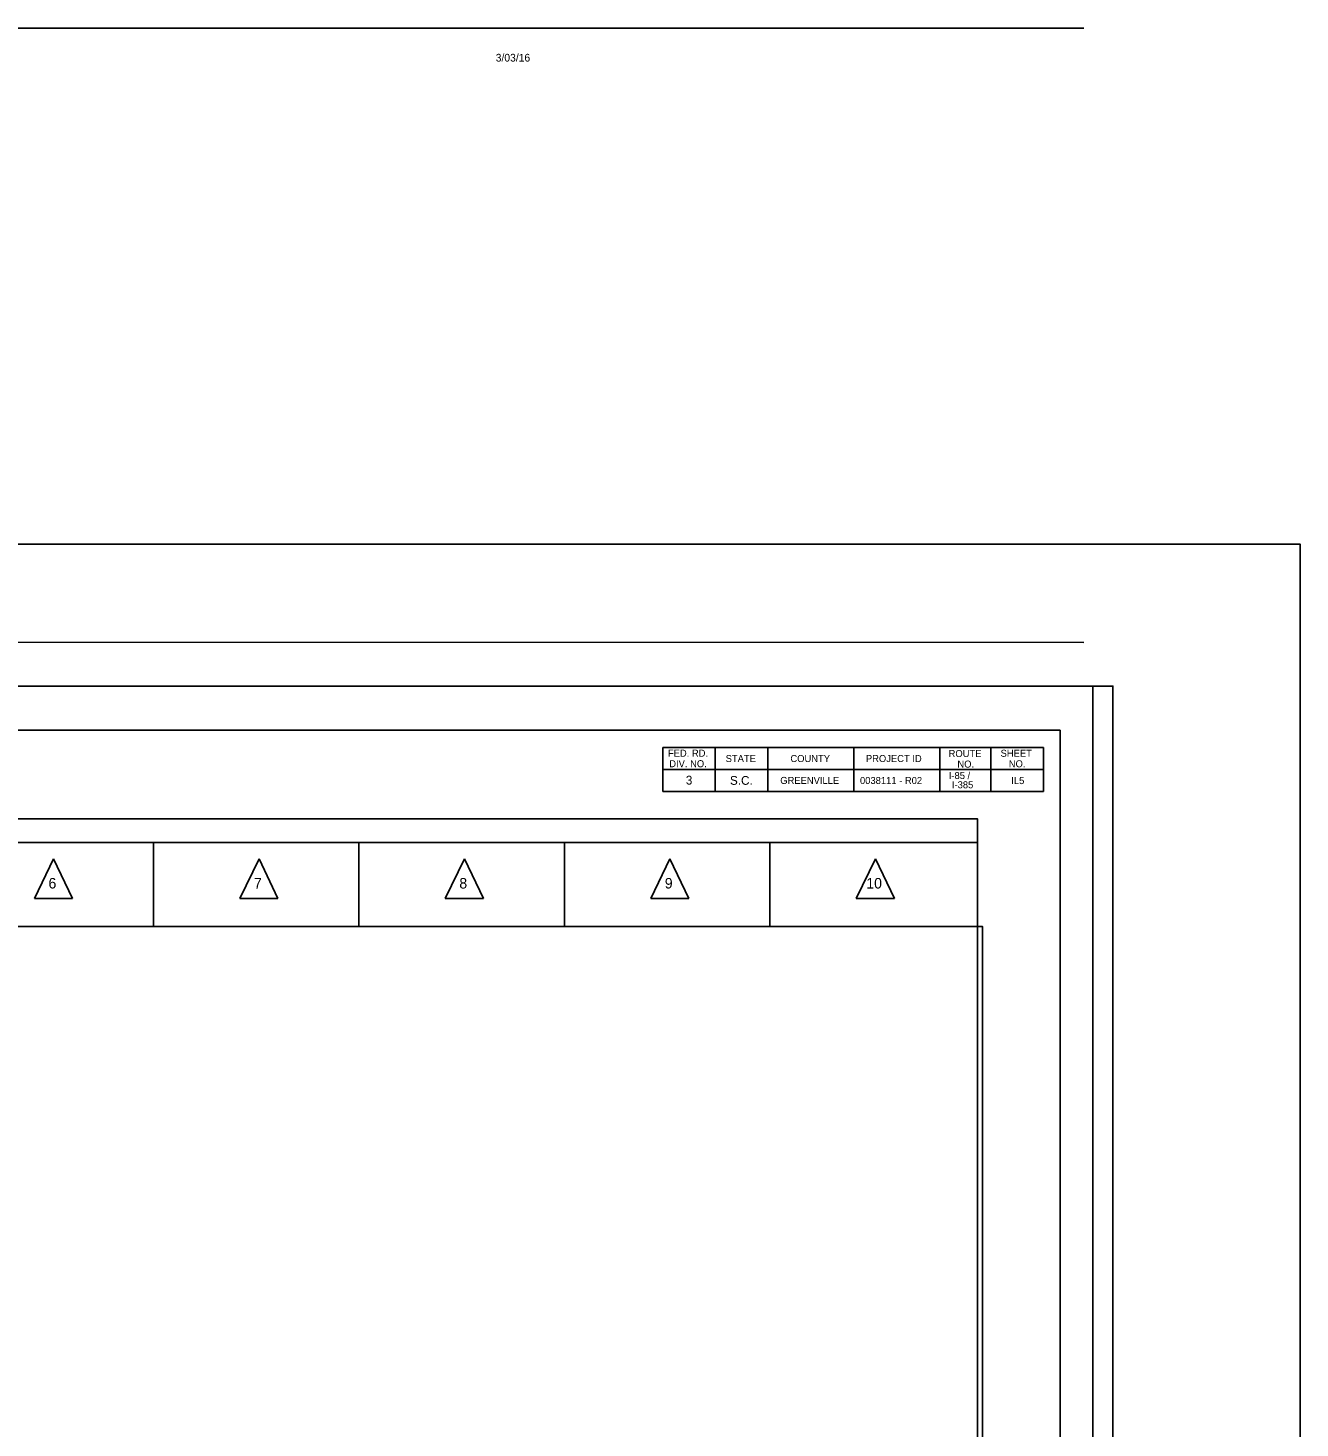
# Model space of a CAD drawing. Extents: x -2251 to 10196, y -13470 to 1199.
# Drawn here: x 1190 to 1915, y -3748 to -2951 of the extents above; entities that cross this region are included whole.
import ezdxf

# ---------------------------------------------------------------- set-up
doc = ezdxf.new("R2010")
doc.units = 0
for name, color, linetype in [('RD_SHT_Bndy', 7, 'Continuous'), ('RD_SHT_Iplotshp', 7, 'Continuous'), ('RD_SHT_Misc1', 7, 'Continuous'), ('RD_SHT_Snap', 7, 'Continuous'), ('RD_SHT_TX', 7, 'Continuous'), ('RD_TX_Misc1', 7, 'Continuous'), ('RD_TX_RoadID', 7, 'Continuous')]:
    doc.layers.add(name, color=color, linetype=linetype)

msp = doc.modelspace()

# ---------------------------------------------------------------- linework, layer by layer
at = {"layer": 'RD_SHT_Bndy'}
for p, q in [((1791.6, -2950.7), (31.6, -2950.65)), ((1791.65, -3300.7), (31.65, -3300.65)), ((1791.65, -3325.65), (31.65, -3325.65)), ((103.1, -3350.65), (1778.1, -3350.65)), ((1778.1, -4400.65), (1778.1, -3350.65)), ((1551.6, -3385.65), (1551.6, -3360.65)), ((1551.6, -3360.65), (1768.6, -3360.65)), ((1581.6, -3360.65), (1581.6, -3385.65)), ((1611.6, -3360.65), (1611.6, -3385.65)), ((1660.6, -3360.65), (1660.6, -3385.65)), ((1709.6, -3360.65), (1709.6, -3385.65)), ((1738.6, -3360.65), (1738.6, -3385.65)), ((1768.6, -3360.65), (1768.6, -3385.65)), ((1551.6, -3373.15), (1768.6, -3373.15)), ((1768.6, -3385.65), (1551.6, -3385.65)), ((153.4, -3414.83), (1731.08, -3414.83)), ((1261.43, -3462.61), (1261.43, -3414.83)), ((1378.52, -3462.61), (1378.52, -3414.83)), ((1495.61, -3462.61), (1495.61, -3414.83)), ((1612.69, -3462.61), (1612.69, -3414.83)), ((1204.5, -3424.06), (1193.55, -3446.58)), ((1215.26, -3446.58), (1204.5, -3424.06)), ((1321.59, -3424.06), (1310.63, -3446.58)), ((1332.35, -3446.58), (1321.59, -3424.06)), ((1438.68, -3424.06), (1427.72, -3446.58)), ((1449.44, -3446.58), (1438.68, -3424.06)), ((1555.76, -3424.06), (1544.81, -3446.58)), ((1566.52, -3446.58), (1555.76, -3424.06)), ((1672.85, -3424.06), (1661.89, -3446.58)), ((1683.61, -3446.58), (1672.85, -3424.06)), ((1193.55, -3446.58), (1215.26, -3446.58)), ((1310.63, -3446.58), (1332.35, -3446.58)), ((1427.72, -3446.58), (1449.44, -3446.58)), ((1544.81, -3446.58), (1566.52, -3446.58)), ((1661.89, -3446.58), (1683.61, -3446.58)), ((153.4, -3462.61), (1731.08, -3462.61))]:
    msp.add_line(p, q, dxfattribs=at)
msp.add_lwpolyline([(153.4, -3401.26), (1731.08, -3401.26), (1731.08, -4265.57), (153.4, -4265.57)], close=True, dxfattribs=at)
at = {"layer": 'RD_SHT_Iplotshp'}
msp.add_lwpolyline([(-3.35, -3325.65), (1796.65, -3325.65), (1796.65, -4425.65), (-3.35, -4425.65)], close=True, dxfattribs=at)
at = {"layer": 'RD_SHT_Misc1'}
msp.add_lwpolyline([(1796.65, -4425.65), (1796.68, -3325.65), (96.68, -3325.6), (96.65, -4425.6)], close=True, dxfattribs=at)
at = {"layer": 'RD_SHT_Snap'}
msp.add_lwpolyline([(8.15, -3325.65), (1808.15, -3325.65), (1808.15, -4425.65), (8.15, -4425.65)], close=True, dxfattribs=at)
at = {"layer": 'RD_TX_Misc1'}
msp.add_lwpolyline([(-127.02, -3244.69), (1914.78, -3244.69), (1914.78, -4546.07), (-127.02, -4546.07)], close=True, dxfattribs=at)
at = {"layer": 'RD_TX_RoadID'}
msp.add_lwpolyline([(150.54, -4265.73), (1733.93, -4265.73), (1733.93, -3462.61), (150.54, -3462.61)], close=True, dxfattribs=at)

# ---------------------------------------------------------------- texts
at = {"layer": 'RD_SHT_Bndy'}
for s, height, p in [('FED. RD.', 4, (1554.59, -3365.85)), ('STATE', 4, (1587.49, -3368.9)), ('COUNTY', 4, (1624.39, -3368.9)), ('PROJECT ID', 4, (1667.41, -3368.9)), ('ROUTE', 4, (1714.54, -3366.05)), ('SHEET', 4, (1744.14, -3365.9)), ('DIV. NO.', 4, (1555.34, -3371.85)), ('NO.', 4, (1719.54, -3372.05)), ('NO.', 4, (1748.84, -3371.9)), ('3', 5, (1564.79, -3381.72)), ('S.C.', 5, (1589.94, -3381.87)), ('GREENVILLE', 4, (1618.6, -3381.37)), ('0038111 - R02', 4, (1664.04, -3381.4)), ('I-85 /', 4, (1714.64, -3378.6)), ('I-385', 4, (1716.41, -3383.85)), ('IL5', 4, (1750.25, -3381.46)), ('6', 6, (1201.61, -3440.96)), ('7', 6, (1318.7, -3440.96)), ('8', 6, (1435.73, -3440.96)), ('9', 6, (1552.81, -3440.96)), ('10', 6, (1667.64, -3440.96))]:
    msp.add_text(s, height=height, dxfattribs=at).set_placement(p)
at = {"layer": 'RD_SHT_TX'}
msp.add_text('3/03/16', height=4.408, dxfattribs=at).set_placement((1456.45, -2969.78))

doc.saveas('drawing.dxf')
